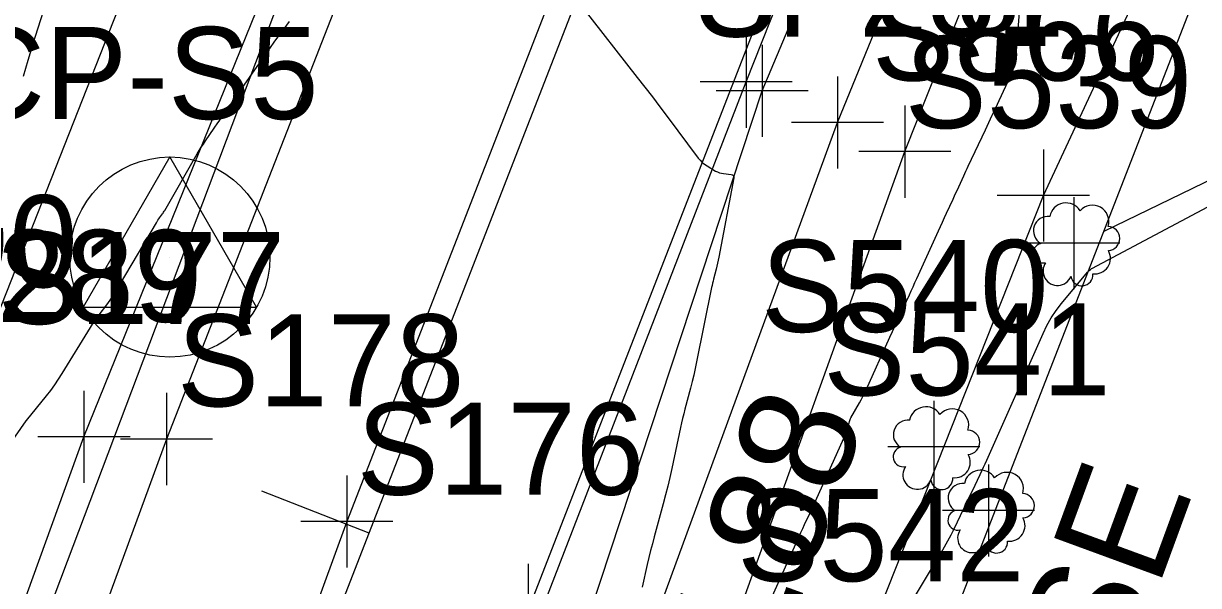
# Model space of a CAD drawing. Extents: x 816928 to 825690, y 436959 to 448212.
# Drawn here: x 818743.3 to 818794.3, y 444705.8 to 444730.2 of the extents above; entities that cross this region are included whole.
import ezdxf

# ---------------------------------------------------------------- set-up
doc = ezdxf.new("R2010")
doc.units = 0
for name, color, linetype in [('SURVEY - CENTERLINE - Preliminary', 7, 'Continuous'), ('SURVEY - CENTERLINE - Preliminary Text', 7, 'Continuous'), ('SURVEY - CONTOURS - Intermediate with optional Text', 7, 'Continuous'), ('SURVEY - CONTROL with Text', 7, 'Continuous'), ('SURVEY - DRAINAGE - Area Shapes', 7, 'Continuous'), ('SURVEY - DRAINAGE - Pipes and Culverts Text', 7, 'Continuous'), ('SURVEY - DTM - Breaklines', 7, 'Continuous'), ('SURVEY - DTM - Breaklines - Points - Locators', 7, 'Continuous'), ('SURVEY - DTM - Breaklines - Points - Numbers', 7, 'Continuous'), ('SURVEY - NON-TRANSPORTATION - Features Text', 7, 'Continuous'), ('SURVEY - PROPERTY - Parcels', 7, 'Continuous'), ('SURVEY - PROPERTY - ROW Lines', 7, 'Continuous'), ('SURVEY - PROPERTY - ROW Lines Text', 7, 'Continuous'), ('SURVEY - TRANSPORTATION - Roads', 7, 'Continuous'), ('SURVEY - TRANSPORTATION - Roads - Points - Locators', 7, 'Continuous'), ('SURVEY - TRANSPORTATION - Roads - Points - Numbers', 7, 'Continuous'), ('SURVEY - UTILITIES - Gas with Text', 7, 'Continuous'), ('SURVEY - UTILITIES - Water - Points - Locators', 7, 'Continuous'), ('SURVEY - UTILITIES - Water with Text', 7, 'Continuous'), ('SURVEY - VEGETATION - Features - Points - Locators', 7, 'Continuous'), ('SURVEY - VEGETATION - Features - Points - Numbers', 7, 'Continuous'), ('SURVEY - VEGETATION - Features with Text', 7, 'Continuous')]:
    doc.layers.add(name, color=color, linetype=linetype)

msp = doc.modelspace()

# ---------------------------------------------------------------- linework, layer by layer
at = {"layer": 'SURVEY - CENTERLINE - Preliminary'}
msp.add_line((818740.593, 444662.662), (818873.377, 445003.735), dxfattribs=at)
at = {"layer": 'SURVEY - CENTERLINE - Preliminary Text'}
msp.add_line((818758.284, 444708.102), (818753.624, 444709.916), dxfattribs=at)
at = {"layer": 'SURVEY - CONTOURS - Intermediate with optional Text'}
for points in [[(818775.477, 444704.628), (818776.902, 444707.793), (818776.979, 444707.962), (818777.055, 444708.131), (818777.132, 444708.299), (818777.21, 444708.467), (818777.464, 444709.016), (818777.518, 444709.133), (818777.572, 444709.251), (818777.626, 444709.369), (818777.68, 444709.487), (818779.045, 444712.512), (818779.069, 444712.57), (818779.09, 444712.629), (818779.107, 444712.69), (818779.121, 444712.751), (818779.161, 444712.953), (818779.171, 444712.996), (818779.185, 444713.037), (818779.202, 444713.078), (818779.222, 444713.116), (818779.591, 444713.76), (818779.669, 444713.899), (818779.743, 444714.039), (818779.813, 444714.181), (818779.881, 444714.325), (818780.916, 444716.615), (818781.031, 444716.869), (818781.147, 444717.123), (818781.263, 444717.376), (818781.381, 444717.63), (818781.764, 444718.456), (818781.846, 444718.633), (818781.928, 444718.81), (818782.009, 444718.988), (818782.09, 444719.165), (818783.028, 444721.239), (818783.115, 444721.429), (818783.202, 444721.62), (818783.29, 444721.81), (818783.378, 444722), (818783.666, 444722.62), (818783.728, 444722.754), (818783.789, 444722.887), (818783.85, 444723.02), (818783.911, 444723.153), (818784.128, 444723.633), (818784.175, 444723.735), (818784.222, 444723.838), (818784.27, 444723.94), (818784.318, 444724.042), (818785.067, 444725.626), (818785.216, 444725.943), (818785.366, 444726.26), (818785.516, 444726.578), (818785.665, 444726.895), (818786.152, 444727.932), (818786.246, 444728.157), (818786.318, 444728.388), (818786.369, 444728.624), (818786.399, 444728.867), (818786.602, 444731.497)], [(818744.239, 444731.131), (818743.66, 444729.324), (818743.552, 444728.981), (818743.449, 444728.635), (818743.351, 444728.289), (818743.257, 444727.941)], [(818767.509, 444731.004), (818769.937, 444727.907), (818770.268, 444727.484), (818770.596, 444727.058), (818770.921, 444726.63), (818771.244, 444726.201), (818772.589, 444724.403), (818772.672, 444724.303), (818772.764, 444724.211), (818772.864, 444724.13), (818772.973, 444724.058), (818773.342, 444723.838), (818773.423, 444723.795), (818773.507, 444723.762), (818773.594, 444723.739), (818773.684, 444723.726), (818774.02, 444723.693), (818774.081, 444723.678), (818774.121, 444723.647), (818774.14, 444723.6), (818774.137, 444723.537), (818773.48, 444720.096), (818773.454, 444719.963), (818773.426, 444719.832), (818773.396, 444719.7), (818773.363, 444719.57), (818773.255, 444719.143), (818773.232, 444719.051), (818773.211, 444718.959), (818773.19, 444718.867), (818773.171, 444718.775), (818772.516, 444715.54), (818772.456, 444715.255), (818772.392, 444714.971), (818772.324, 444714.687), (818772.251, 444714.405), (818772.008, 444713.484), (818771.957, 444713.287), (818771.909, 444713.088), (818771.863, 444712.89), (818771.819, 444712.69), (818771.437, 444710.901), (818771.353, 444710.519), (818771.263, 444710.137), (818771.168, 444709.757), (818771.067, 444709.379), (818770.675, 444707.941), (818770.595, 444707.641), (818770.518, 444707.341), (818770.446, 444707.04), (818770.376, 444706.738), (818770.155, 444705.749)], [(818742.46, 444711.647), (818743.382, 444712.982), (818743.383, 444712.983), (818743.384, 444712.985), (818743.385, 444712.987), (818743.386, 444712.988), (818743.39, 444712.994), (818743.391, 444712.995), (818743.392, 444712.996), (818743.393, 444712.997), (818743.394, 444712.998), (818744.268, 444714.071), (818744.451, 444714.304), (818744.626, 444714.542), (818744.794, 444714.786), (818744.953, 444715.036), (818746.176, 444717.031), (818746.267, 444717.174), (818746.36, 444717.314), (818746.458, 444717.452), (818746.559, 444717.588), (818746.895, 444718.026), (818746.965, 444718.121), (818747.033, 444718.217), (818747.098, 444718.316), (818747.159, 444718.417), (818749.041, 444721.591), (818749.075, 444721.646), (818749.109, 444721.7), (818749.145, 444721.753), (818749.182, 444721.805), (818749.306, 444721.975), (818749.332, 444722.012), (818749.357, 444722.049), (818749.381, 444722.087), (818749.404, 444722.126), (818750.819, 444724.581), (818750.904, 444724.726), (818750.992, 444724.868), (818751.082, 444725.009), (818751.175, 444725.148), (818751.548, 444725.696), (818751.581, 444725.744), (818751.615, 444725.792), (818751.649, 444725.841), (818751.683, 444725.888), (818751.796, 444726.045), (818751.82, 444726.078), (818751.844, 444726.112), (818751.868, 444726.145), (818751.891, 444726.179), (818753.517, 444728.528), (818753.677, 444728.758), (818753.839, 444728.986), (818754.002, 444729.212), (818754.167, 444729.438), (818754.708, 444730.173), (818754.823, 444730.331)], [(818781.486, 444704.469), (818783.146, 444707.238), (818783.297, 444707.497), (818783.442, 444707.759), (818783.581, 444708.024), (818783.714, 444708.293), (818784.138, 444709.176), (818784.228, 444709.365), (818784.319, 444709.555), (818784.41, 444709.744), (818784.501, 444709.933), (818784.846, 444710.652), (818784.919, 444710.806), (818784.992, 444710.961), (818785.063, 444711.117), (818785.132, 444711.273), (818787.572, 444716.774), (818787.741, 444717.122), (818787.931, 444717.456), (818788.145, 444717.775), (818788.38, 444718.081), (818789.499, 444719.436), (818789.516, 444719.456), (818789.534, 444719.475), (818789.553, 444719.493), (818789.573, 444719.51), (818789.639, 444719.564), (818789.654, 444719.575), (818789.669, 444719.586), (818789.684, 444719.595), (818789.7, 444719.604), (818794.733, 444722.281)]]:
    msp.add_lwpolyline(points, dxfattribs=at)
at = {"layer": 'SURVEY - CONTROL with Text'}
for p, q in [((818749.627, 444724.447), (818745.86, 444717.922)), ((818753.394, 444717.922), (818749.627, 444724.447)), ((818749.627, 444720.097), (818749.627, 444720.097)), ((818745.86, 444717.922), (818753.394, 444717.922))]:
    msp.add_line(p, q, dxfattribs=at)
msp.add_circle((818749.627, 444720.097), 4.35, dxfattribs=at)
at = {"layer": 'SURVEY - DRAINAGE - Area Shapes'}
msp.add_line((818740.593, 444662.662), (818873.377, 445003.735), dxfattribs=at)
at = {"layer": 'SURVEY - DTM - Breaklines'}
for points in [[(818674.595, 444526.594), (818691.482, 444572.447), (818707.878, 444620.16), (818723.912, 444667.229), (818740.639, 444713.784), (818759.184, 444760.748), (818780.007, 444808.946), (818796, 444863.508), (818810.795, 444901.838), (818829.914, 444950.597), (818849.199, 444995.994), (818867.147, 445042.084), (818885.66, 445087.698), (818887.911, 445097.82), (818891.186, 445123.694), (818896.177, 445136.062), (818917.377, 445175.791)], [(818676.308, 444526.27), (818695.981, 444570.723), (818712.39, 444618.98), (818728.83, 444665.288), (818745.895, 444712.28), (818764.807, 444759.048), (818784.52, 444806.667), (818801.14, 444861.811), (818818.983, 444900.087), (818838.243, 444946.217), (818855.869, 444992.165), (818873.704, 445038.582), (818892.288, 445085.577), (818894.59, 445096.559), (818896.482, 445123.312), (818901.189, 445133.745), (818919.534, 445174.233), (818947.165, 445168.058)], [(818958.139, 445160.069), (818932.682, 445121.487), (818907.758, 445078.468), (818886.279, 445033.29), (818867.243, 444986.881), (818848.651, 444941.091), (818830.333, 444893.785), (818812.367, 444847.898), (818794.091, 444801.186), (818775.412, 444755.123), (818757.321, 444708.609), (818740.17, 444661.598), (818740.227, 444661.382), (818723.384, 444614.358), (818707.23, 444567.59), (818689.196, 444521.032)], [(818762.26, 444679.495), (818761.013, 444680.75), (818760.417, 444681.978), (818775.364, 444727.321), (818792.709, 444768.456), (818808.486, 444810.608), (818819.126, 444828.133), (818819.216, 444833.149)], [(818765.717, 444680.649), (818781.569, 444724.679), (818797.725, 444765.305), (818816.693, 444806.888), (818825.356, 444823.941), (818831.974, 444830.742)], [(818762.42, 444681.66), (818778.642, 444725.941), (818795.378, 444766.892), (818813.957, 444808.436), (818822.628, 444825.433)], [(818762.26, 444679.495), (818762.86, 444679.092), (818769.805, 444677.881), (818787.587, 444722.771), (818806.244, 444762.813), (818825.657, 444804.038), (818838.758, 444818.112)]]:
    msp.add_lwpolyline(points, dxfattribs=at)
at = {"layer": 'SURVEY - DTM - Breaklines - Points - Locators'}
for p, q in [((818775.364, 444729.321), (818775.364, 444725.321)), ((818778.642, 444727.941), (818778.642, 444723.941)), ((818777.364, 444727.321), (818773.364, 444727.321)), ((818781.569, 444726.679), (818781.569, 444722.679)), ((818780.642, 444725.941), (818776.642, 444725.941)), ((818783.569, 444724.679), (818779.569, 444724.679)), ((818787.587, 444724.771), (818787.587, 444720.771)), ((818789.587, 444722.771), (818785.587, 444722.771)), ((818745.895, 444714.28), (818745.895, 444710.28)), ((818747.895, 444712.28), (818743.895, 444712.28)), ((818757.321, 444710.609), (818757.321, 444706.609)), ((818759.321, 444708.609), (818755.321, 444708.609))]:
    msp.add_line(p, q, dxfattribs=at)
at = {"layer": 'SURVEY - PROPERTY - Parcels'}
msp.add_line((818764.01, 444653.9), (818816.414, 444788.507), dxfattribs=at)
at = {"layer": 'SURVEY - PROPERTY - ROW Lines'}
msp.add_line((818764.01, 444653.9), (818896.674, 444994.666), dxfattribs=at)
at = {"layer": 'SURVEY - PROPERTY - ROW Lines Text'}
msp.add_lwpolyline([(818879.294, 444764.426), (818790.212, 444721.204)], dxfattribs=at)
at = {"layer": 'SURVEY - TRANSPORTATION - Roads'}
for points in [[(818965.229, 445155.363), (818951.411, 445165.352), (818926.02, 445127.499), (818900.328, 445082.499), (818878.311, 445036.446), (818858.824, 444990.147), (818840.564, 444944.187), (818822.719, 444897.894), (818804.417, 444851.441), (818785.945, 444804.727), (818767.422, 444758.087), (818749.481, 444712.19), (818731.94, 444664.32), (818715.455, 444617.821), (818698.912, 444570.495), (818680.86, 444523.941)], [(818965.229, 445155.363), (818938.616, 445116.052), (818915.349, 445074.624), (818893.365, 445028.079), (818874.295, 444982.228), (818856.423, 444936.819), (818838.526, 444889.933), (818820.316, 444844.098), (818801.626, 444797.247), (818782.894, 444750.293), (818765.195, 444704.769), (818748.054, 444657.938), (818731.68, 444611.01), (818715.158, 444564.483), (818697.018, 444517.159)], [(818965.229, 445155.363), (818938.616, 445116.052), (818915.349, 445074.624), (818898.78, 445039.544), (818893.365, 445028.079), (818891.235, 445022.959), (818874.295, 444982.228), (818856.423, 444936.819), (818838.526, 444889.933), (818820.316, 444844.098), (818801.626, 444797.247), (818782.894, 444750.293), (818765.195, 444704.769), (818757.626, 444684.091), (818748.679, 444659.647), (818748.054, 444657.938), (818731.68, 444611.01), (818715.158, 444564.483), (818697.018, 444517.159)]]:
    msp.add_lwpolyline(points, dxfattribs=at)
at = {"layer": 'SURVEY - TRANSPORTATION - Roads - Points - Locators'}
for p, q in [((818749.481, 444714.19), (818749.481, 444710.19)), ((818751.481, 444712.19), (818747.481, 444712.19)), ((818765.195, 444706.769), (818765.195, 444702.769))]:
    msp.add_line(p, q, dxfattribs=at)
at = {"layer": 'SURVEY - UTILITIES - Gas with Text'}
msp.add_lwpolyline([(818677.986, 444524.549), (818704.191, 444595.26), (818728.998, 444664.068), (818764.629, 444758.415), (818803.581, 444855.269), (818837.396, 444944.843), (818872.359, 445029.489), (818905.906, 445097.999), (818946.069, 445164.692)], dxfattribs=at)
at = {"layer": 'SURVEY - UTILITIES - Water - Points - Locators'}
for p, q in [((818774.671, 444729.707), (818774.671, 444725.707)), ((818776.671, 444727.707), (818772.671, 444727.707))]:
    msp.add_line(p, q, dxfattribs=at)
at = {"layer": 'SURVEY - UTILITIES - Water with Text'}
msp.add_lwpolyline([(818697.069, 444516.079), (818707.886, 444542.766), (818724.217, 444588.304), (818740.773, 444636.214), (818757.106, 444682.286), (818774.671, 444727.707), (818803.235, 444799.745), (818822.09, 444847.157)], dxfattribs=at)
at = {"layer": 'SURVEY - VEGETATION - Features - Points - Locators'}
for p, q in [((818788.915, 444722.701), (818788.915, 444718.701)), ((818790.915, 444720.701), (818786.915, 444720.701)), ((818782.826, 444713.844), (818782.826, 444709.844)), ((818784.826, 444711.844), (818780.826, 444711.844)), ((818785.204, 444711.087), (818785.204, 444707.087)), ((818787.204, 444709.087), (818783.204, 444709.087))]:
    msp.add_line(p, q, dxfattribs=at)
at = {"layer": 'SURVEY - VEGETATION - Features with Text'}
for centre in [(818788.932, 444720.707), (818782.844, 444711.849), (818785.221, 444709.092)]:
    msp.add_circle(centre, 0.022, dxfattribs=at)
for centre, radius, start, end in [((818788.572, 444721.732), 0.719, 31.9683, 169.4925), ((818789.718, 444721.641), 0.714, 342.8641, 138.7026), ((818787.789, 444721.237), 0.631, 82.9155, 239.7044), ((818790.383, 444720.905), 0.527, 273.117, 88.1173), ((818787.583, 444720.274), 0.433, 105.0317, 283.7773), ((818789.823, 444720.041), 0.679, 262.9581, 29.8037), ((818788.202, 444719.493), 0.629, 145.0523, 338.472), ((818789.262, 444719.326), 0.479, 187.671, 4.9902), ((818782.484, 444712.874), 0.719, 31.9683, 169.4925), ((818783.63, 444712.784), 0.714, 342.8641, 138.7026), ((818781.701, 444712.379), 0.631, 82.9155, 239.7044), ((818784.295, 444712.047), 0.527, 273.117, 88.1173), ((818781.495, 444711.417), 0.433, 105.0317, 283.7773), ((818783.735, 444711.184), 0.679, 262.9581, 29.8037), ((818782.114, 444710.635), 0.629, 145.0523, 338.472), ((818784.861, 444710.118), 0.719, 31.9683, 169.4925), ((818786.007, 444710.027), 0.714, 342.8641, 138.7026), ((818783.174, 444710.468), 0.479, 187.671, 4.9902), ((818784.078, 444709.623), 0.631, 82.9155, 239.7044), ((818786.673, 444709.29), 0.527, 273.117, 88.1173), ((818783.872, 444708.66), 0.433, 105.0317, 283.7773), ((818786.112, 444708.427), 0.679, 262.9581, 29.8037), ((818784.491, 444707.879), 0.629, 145.0523, 338.472), ((818785.552, 444707.712), 0.479, 187.671, 4.9902)]:
    msp.add_arc(centre, radius, start, end, dxfattribs=at)

# ---------------------------------------------------------------- texts
at = {"layer": 'SURVEY - CONTROL with Text'}
msp.add_text('CP-S5', height=4, dxfattribs=at).set_placement((818740.339, 444726.097))
at = {"layer": 'SURVEY - DRAINAGE - Pipes and Culverts Text'}
msp.add_text('INV-315.88', height=5, rotation=70.2011, dxfattribs=at).set_placement((818768.418, 444681.245))
at = {"layer": 'SURVEY - DTM - Breaklines - Points - Numbers'}
for s, p in [('SP231', (818772.439, 444729.679)), ('S866', (818780.141, 444727.771)), ('S290', (818733.13, 444718.784)), ('S289', (818738.543, 444717.28)), ('S178', (818749.938, 444713.609))]:
    msp.add_text(s, height=4, dxfattribs=at).set_placement(p)
at = {"layer": 'SURVEY - NON-TRANSPORTATION - Features Text'}
msp.add_text('BIRDHOUSE', height=5, rotation=69.8637, dxfattribs=at).set_placement((818780.413, 444672.522))
at = {"layer": 'SURVEY - TRANSPORTATION - Roads - Points - Numbers'}
for s, p in [('S177', (818742.145, 444717.19)), ('S176', (818757.749, 444709.769))]:
    msp.add_text(s, height=4, dxfattribs=at).set_placement(p)
at = {"layer": 'SURVEY - VEGETATION - Features - Points - Numbers'}
for s, p in [('S539', (818781.563, 444725.701)), ('S540', (818775.317, 444716.844)), ('S541', (818778.026, 444714.087)), ('S542', (818774.282, 444706.01))]:
    msp.add_text(s, height=4, dxfattribs=at).set_placement(p)

doc.saveas('drawing.dxf')
